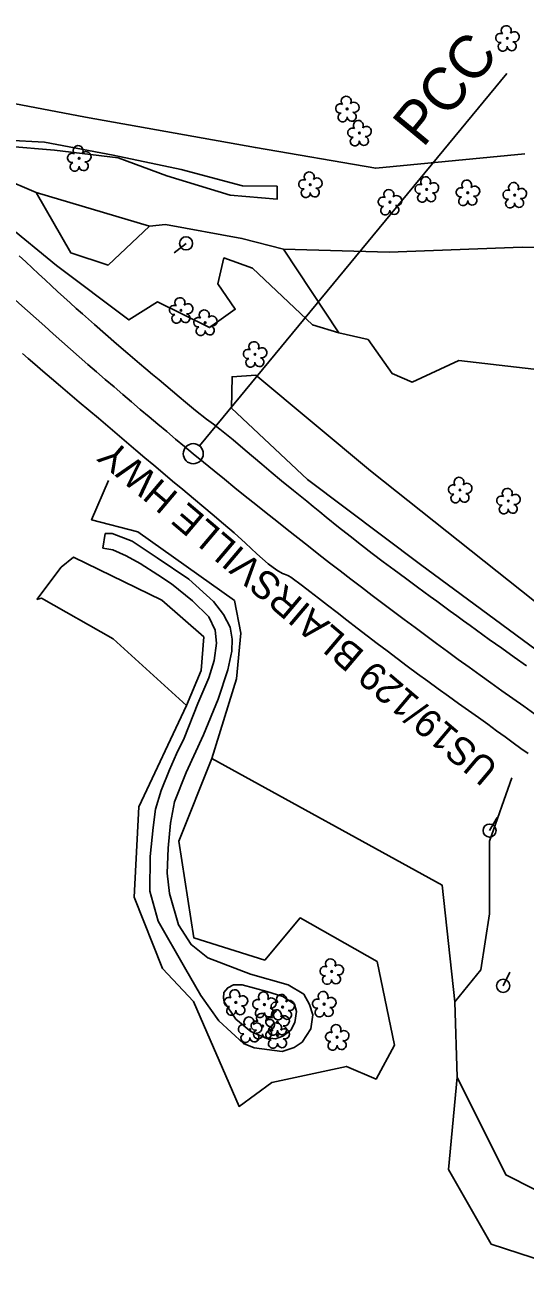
# Model space of a CAD drawing. Extents: x 477009 to 479892, y 492858 to 496862.
# Drawn here: x 479085.5 to 479272.5, y 493587.2 to 494052.3 of the extents above; entities that cross this region are included whole.
import ezdxf

# ---------------------------------------------------------------- set-up
doc = ezdxf.new("R2010")
doc.units = 0
for name, color, linetype in [('Exist Horizontal Alignment', 7, 'Continuous'), ('Exist Other Culture Fence Line', 7, 'Continuous'), ('Exist Roads EOP', 7, 'Continuous'), ('Exist Roads EOP Text', 7, 'Continuous'), ('Exist Roads Soil', 7, 'Continuous'), ('Exist Utilities Power Pole CELL', 7, 'Continuous'), ('Exist Vegetation Hedge Row', 7, 'Continuous'), ('Exist Vegetation Tree CELL', 7, 'Continuous'), ('Exist Vegetation Woods Line', 7, 'Continuous')]:
    doc.layers.add(name, color=color, linetype=linetype)

msp = doc.modelspace()

# ---------------------------------------------------------------- linework, layer by layer
at = {"layer": 'Exist Horizontal Alignment'}
msp.add_line((479150.84, 493895.18), (479265.62, 494034.24), dxfattribs=at)
msp.add_circle((479148.46, 493892.29), 3.75, dxfattribs=at)
for centre, radius, start, end in [((480415.92, 495427.95), 1991.17, 222.54643, 230.46528), ((480448.9, 495467.9), 2042.96, 230.46528, 239.46392)]:
    msp.add_arc(centre, radius, start, end, dxfattribs=at)
at = {"layer": 'Exist Other Culture Fence Line'}
for points in [[(479108.16, 494017.94), (479070.79, 494024.96), (479052.06, 494028.2), (479035.55, 494044.67), (479005.51, 494074.07), (478956.05, 494123.48), (478945.66, 494161.44), (478974.21, 494187.61), (479002.57, 494213.48)], [(479108.16, 494017.94), (479171.66, 494006.53), (479216.64, 493998.87), (479272.39, 494004.19)]]:
    msp.add_lwpolyline(points, dxfattribs=at)
at = {"layer": 'Exist Roads EOP'}
for points in [[(479273.02, 493813.09), (479268.38, 493816.36), (479263.76, 493819.66), (479259.12, 493822.99), (479254.37, 493826.41), (479251.95, 493828.15), (479249.5, 493829.92), (479247.02, 493831.72), (479244.52, 493833.54), (479241.99, 493835.38), (479239.47, 493837.22), (479237.01, 493839.02), (479232.25, 493842.48), (479227.75, 493845.78), (479223.52, 493848.92), (479219.45, 493851.98), (479215.38, 493855.06), (479211.29, 493858.21), (479207.12, 493861.47), (479202.78, 493864.92), (479198.14, 493868.65), (479195.74, 493870.59), (479193.31, 493872.56), (479190.85, 493874.56), (479188.36, 493876.59), (479185.92, 493878.57), (479181.49, 493882.21), (479177.6, 493885.42), (479174.1, 493888.33), (479170.92, 493891), (479167.8, 493893.65), (479163.35, 493897.42), (479160.82, 493899.5), (479158.43, 493901.39), (479155.97, 493903.29), (479153.43, 493905.23), (479149.31, 493908.45), (479145.5, 493911.58), (479143.16, 493913.54), (479140.68, 493915.63), (479138.2, 493917.72), (479135.7, 493919.82), (479133.2, 493921.91), (479130.74, 493923.98), (479128.38, 493925.97), (479123.95, 493929.75), (479119.77, 493933.35), (479115.68, 493936.87), (479111.5, 493940.51), (479107.04, 493944.46), (479104.73, 493946.52), (479102.41, 493948.61), (479100.09, 493950.72), (479097.76, 493952.85), (479095.41, 493955), (479093.04, 493957.18), (479090.65, 493959.39), (479088.24, 493961.63), (479085.82, 493963.88), (479083.41, 493966.11)], [(479273.65, 493780.38), (479270.93, 493782.31), (479268.06, 493784.37), (479265.03, 493786.58), (479261.85, 493788.9), (479258.52, 493791.31), (479255.03, 493793.8), (479251.39, 493796.39), (479247.65, 493799.04), (479243.86, 493801.75), (479240.02, 493804.52), (479236.13, 493807.33), (479232.24, 493810.17), (479228.41, 493813.01), (479224.62, 493815.83), (479220.89, 493818.65), (479217.17, 493821.47), (479213.43, 493824.34), (479209.68, 493827.23), (479205.91, 493830.16), (479202.2, 493833.04), (479198.66, 493835.79), (479195.27, 493838.4), (479192.04, 493840.88), (479189.23, 493843.03), (479184.87, 493846.25), (479184.09, 493846.7), (479183.76, 493846.85), (479182.54, 493847.27), (479181.78, 493847.62), (479179.67, 493848.88), (479176.5, 493851.2), (479172.16, 493854.92), (479167.96, 493858.86), (479163.74, 493862.76), (479159.8, 493866.17), (479155.52, 493869.74), (479152.38, 493872.36), (479148.56, 493875.53), (479144.51, 493878.89), (479140.68, 493882.08), (479137.07, 493885.12), (479133.66, 493887.98), (479130.34, 493890.79), (479126.97, 493893.65), (479123.54, 493896.57), (479120.05, 493899.53), (479116.53, 493902.53), (479112.99, 493905.53), (479109.44, 493908.54), (479105.86, 493911.56), (479102.32, 493914.54), (479098.87, 493917.46), (479095.52, 493920.32), (479092.25, 493923.1), (479089.26, 493925.68), (479086.73, 493927.88), (479084.65, 493929.72)]]:
    msp.add_lwpolyline(points, dxfattribs=at)
at = {"layer": 'Exist Roads Soil'}
for points in [[(479115.47, 493862.54), (479118.17, 493862.52), (479125.58, 493859.66), (479135.01, 493853.38), (479146.79, 493845.44), (479156.04, 493837.13), (479159.74, 493832.23), (479162.21, 493827.49), (479163.04, 493823.1), (479162.93, 493818.6), (479161.34, 493811.63), (479157.76, 493800.7), (479152.24, 493787.36), (479145.79, 493773.32), (479141.47, 493762.36), (479139.91, 493754.41), (479139.03, 493745.1), (479138.68, 493735.69), (479139.53, 493728.14), (479142.95, 493716.46), (479147.68, 493709.09), (479153.89, 493704.09), (479169.8, 493698.05), (479183.93, 493694.02), (479189.75, 493690.55), (479191.96, 493686.74), (479193.12, 493682.84), (479192.44, 493677.59), (479189.13, 493672.66), (479186.17, 493670.59), (479181.75, 493669.19), (479171.25, 493670.54), (479167.28, 493672.1), (479158, 493680.62), (479151.25, 493690.09), (479145.24, 493700.61), (479135.39, 493717.85), (479132.28, 493729.06), (479132.29, 493741.91), (479133.52, 493752.81), (479134.29, 493759.61), (479136.4, 493766.63), (479139.63, 493774.27), (479142.25, 493780.22), (479145, 493786.14), (479150.14, 493799.06), (479154.26, 493808.63), (479156.32, 493815.04), (479157.12, 493821.63), (479156.69, 493826.48), (479154.24, 493831.35), (479148.16, 493837.35), (479140.35, 493843.73), (479135.27, 493847.12), (479128.62, 493851.25), (479123.39, 493854.2), (479118.35, 493856.45), (479114.67, 493857.07), (479115.47, 493862.54)], [(479159.98, 493687.75), (479164.43, 493681.27), (479169.94, 493676.57), (479175.04, 493674.43), (479179.18, 493673.84), (479181.96, 493674.9), (479184.92, 493677.07), (479186.43, 493680), (479187.08, 493684.1), (479186.29, 493686.82), (479181.92, 493689.67), (479175.94, 493691.53), (479166.8, 493694.01), (479163.54, 493694), (479161.32, 493692.97), (479159.94, 493691.13), (479159.76, 493689.09), (479159.98, 493687.75)]]:
    msp.add_lwpolyline(points, dxfattribs=at)
at = {"layer": 'Exist Utilities Power Pole CELL'}
for p, q in [((479145.76, 493970.8), (479141.37, 493967.28)), ((479145.76, 493970.8), (479145.76, 493970.8)), ((479259.22, 493751.62), (479262.06, 493756.47)), ((479259.22, 493751.62), (479259.22, 493751.62)), ((479264.31, 493693.67), (479266.8, 493698.71)), ((479264.31, 493693.67), (479264.31, 493693.67))]:
    msp.add_line(p, q, dxfattribs=at)
for centre in [(479145.76, 493970.8), (479259.22, 493751.62), (479264.31, 493693.67)]:
    msp.add_circle(centre, 2.45, dxfattribs=at)
at = {"layer": 'Exist Vegetation Hedge Row'}
for points in [[(479096.63, 494005.63), (479078.72, 494007.07), (479064.9, 494009.62), (479055.61, 494011.94), (479052.88, 494010.84), (479049.89, 494007.25), (479044.21, 494012.52), (479046.53, 494016.23), (479052.16, 494014.3), (479055.59, 494012.7), (479063, 494013.98), (479078.8, 494009.34), (479092.9, 494008.55)], [(479092.9, 494008.55), (479118.49, 494003.72), (479143.95, 493998.32), (479166.91, 493992.28), (479179.82, 493992.14), (479179.88, 493987.32), (479162.28, 493988.83), (479138.64, 493995.99), (479120.41, 494002.76), (479096.63, 494005.63)], [(479078.52, 493977.98), (479068.39, 493987.61), (479068.42, 493990.58), (479067.35, 493992.62), (479076.93, 493995.26), (479089.7, 493989.76)], [(479202.84, 493937.4), (479192.99, 493940.45), (479170.55, 493961.53), (479159.94, 493965.4), (479157.61, 493955.73), (479164.16, 493946.19), (479154.57, 493939.38), (479135.06, 493949.04), (479124.4, 493942.25), (479097.29, 493962.49), (479078.52, 493977.98)], [(479132.06, 493977.26), (479138.05, 493977.9), (479166.63, 493972.65), (479182.16, 493968.66)], [(479171.8, 493921.62), (479214.74, 493885.94), (479276, 493837.28), (479371.67, 493764.52), (479365.39, 493760.73), (479353.23, 493765.86), (479299.39, 493802.32), (479233.34, 493850.88), (479191.14, 493882.61), (479162.76, 493909.29), (479162.97, 493921.03), (479171.8, 493921.62)], [(479155.42, 493778.48), (479164.56, 493808.22), (479166.22, 493825.31), (479163.89, 493837.46), (479127.8, 493863.11), (479110.48, 493867.61), (479116.76, 493882.24)], [(479089.96, 493837.85), (479099.11, 493849.98), (479103.69, 493853.62), (479136.77, 493837.68), (479152.39, 493823.9), (479151.44, 493811.41), (479145.89, 493798.32)], [(479267.52, 493771.33), (479259.14, 493747.61), (479259.22, 493720.49), (479255.94, 493699.61), (479246.2, 493687.72)], [(479247.14, 493659.54), (479265.35, 493623.09), (479308.43, 493601.29)]]:
    msp.add_lwpolyline(points, dxfattribs=at)
at = {"layer": 'Exist Vegetation Tree CELL'}
for p, q in [((479265.84, 494047.32), (479265.84, 494047.32)), ((479206, 494021), (479206, 494021)), ((479210.56, 494011.99), (479210.56, 494011.99)), ((479105.8, 494002.55), (479105.8, 494002.55)), ((479192.19, 493992.72), (479192.19, 493992.72)), ((479235.71, 493990.95), (479235.71, 493990.95)), ((479221.95, 493986.18), (479221.95, 493986.18)), ((479251.07, 493989.69), (479251.07, 493989.69)), ((479268.59, 493988.81), (479268.59, 493988.81)), ((479143.86, 493945.81), (479143.86, 493945.81)), ((479152.92, 493941.21), (479152.92, 493941.21)), ((479171.52, 493929.38), (479171.52, 493929.38)), ((479248.17, 493878.76), (479248.17, 493878.76)), ((479266.21, 493874.63), (479266.21, 493874.63)), ((479200.18, 493699.01), (479200.18, 493699.01)), ((479164.37, 493687.46), (479164.37, 493687.46)), ((479175.06, 493686.66), (479175.06, 493686.66)), ((479181.85, 493685.73), (479181.85, 493685.73)), ((479197.38, 493686.83), (479197.38, 493686.83)), ((479174.38, 493678.64), (479174.38, 493678.64)), ((479179.93, 493680.01), (479179.93, 493680.01)), ((479169.66, 493677.32), (479169.66, 493677.32)), ((479179.96, 493675.17), (479179.96, 493675.17)), ((479202.22, 493674.48), (479202.22, 493674.48))]:
    msp.add_line(p, q, dxfattribs=at)
for centre in [(479265.84, 494047.32), (479206, 494021), (479210.56, 494011.99), (479105.8, 494002.55), (479192.19, 493992.72), (479235.71, 493990.95), (479251.07, 493989.69), (479221.95, 493986.18), (479268.59, 493988.81), (479143.86, 493945.81), (479152.92, 493941.21), (479171.52, 493929.38), (479248.17, 493878.76), (479266.21, 493874.63), (479200.18, 493699.01), (479164.37, 493687.46), (479175.06, 493686.66), (479181.85, 493685.73), (479197.38, 493686.83), (479174.38, 493678.64), (479179.93, 493680.01), (479169.66, 493677.32), (479179.96, 493675.17), (479202.22, 493674.48)]:
    msp.add_circle(centre, 0.326, dxfattribs=at)
for centre, radius, start, end in [((479265.45, 494050.2), 1.86, 330.1651, 219.7134), ((479263.23, 494047.48), 1.73, 62.6636, 279.3457), ((479264.13, 494044.2), 1.69, 111.5671, 6.231), ((479267.51, 494044.42), 1.7, 181.2822, 74.56), ((479268.39, 494047.91), 1.9, 257.1011, 134.1999), ((479203.4, 494021.15), 1.73, 62.6636, 279.3457), ((479205.62, 494023.87), 1.86, 330.1651, 219.7134), ((479208.55, 494021.59), 1.9, 257.1011, 134.1999), ((479204.3, 494017.88), 1.69, 111.5671, 6.231), ((479207.67, 494018.1), 1.7, 181.2822, 74.56), ((479207.95, 494012.14), 1.73, 62.6636, 279.3457), ((479210.17, 494014.86), 1.86, 330.1651, 219.7134), ((479213.11, 494012.58), 1.9, 257.1011, 134.1999), ((479208.85, 494008.87), 1.69, 111.5671, 6.231), ((479212.23, 494009.09), 1.7, 181.2822, 74.56), ((479103.2, 494002.7), 1.73, 62.6636, 279.3457), ((479105.42, 494005.42), 1.86, 330.1651, 219.7134), ((479108.35, 494003.14), 1.9, 257.1011, 134.1999), ((479104.1, 493999.43), 1.69, 111.5671, 6.231), ((479107.47, 493999.65), 1.7, 181.2822, 74.56), ((479189.59, 493992.87), 1.73, 62.6636, 279.3457), ((479191.81, 493995.59), 1.86, 330.1651, 219.7134), ((479194.74, 493993.31), 1.9, 257.1011, 134.1999), ((479235.33, 493993.83), 1.86, 330.1651, 219.7134), ((479190.49, 493989.6), 1.69, 111.5671, 6.231), ((479193.86, 493989.82), 1.7, 181.2822, 74.56), ((479221.56, 493989.05), 1.86, 330.1651, 219.7134), ((479233.11, 493991.11), 1.73, 62.6636, 279.3457), ((479238.26, 493991.54), 1.9, 257.1011, 134.1999), ((479248.46, 493989.85), 1.73, 62.6636, 279.3457), ((479250.68, 493992.57), 1.86, 330.1651, 219.7134), ((479253.62, 493990.28), 1.9, 257.1011, 134.1999), ((479265.99, 493988.96), 1.73, 62.6636, 279.3457), ((479268.21, 493991.68), 1.86, 330.1651, 219.7134), ((479271.14, 493989.39), 1.9, 257.1011, 134.1999), ((479219.34, 493986.33), 1.73, 62.6636, 279.3457), ((479224.5, 493986.77), 1.9, 257.1011, 134.1999), ((479234.01, 493987.83), 1.69, 111.5671, 6.231), ((479237.38, 493988.05), 1.7, 181.2822, 74.56), ((479249.36, 493986.57), 1.69, 111.5671, 6.231), ((479252.74, 493986.79), 1.7, 181.2822, 74.56), ((479266.89, 493985.68), 1.69, 111.5671, 6.231), ((479270.26, 493985.91), 1.7, 181.2822, 74.56), ((479220.24, 493983.06), 1.69, 111.5671, 6.231), ((479223.62, 493983.28), 1.7, 181.2822, 74.56), ((479143.47, 493948.68), 1.86, 330.1651, 219.7134), ((479146.41, 493946.4), 1.9, 257.1011, 134.1999), ((479141.25, 493945.96), 1.73, 62.6636, 279.3457), ((479142.15, 493942.69), 1.69, 111.5671, 6.231), ((479145.53, 493942.91), 1.7, 181.2822, 74.56), ((479152.54, 493944.09), 1.86, 330.1651, 219.7134), ((479155.47, 493941.8), 1.9, 257.1011, 134.1999), ((479150.32, 493941.37), 1.73, 62.6636, 279.3457), ((479151.22, 493938.09), 1.69, 111.5671, 6.231), ((479154.6, 493938.31), 1.7, 181.2822, 74.56), ((479171.13, 493932.25), 1.86, 330.1651, 219.7134), ((479168.91, 493929.53), 1.73, 62.6636, 279.3457), ((479174.07, 493929.97), 1.9, 257.1011, 134.1999), ((479169.81, 493926.26), 1.69, 111.5671, 6.231), ((479173.19, 493926.48), 1.7, 181.2822, 74.56), ((479247.78, 493881.63), 1.86, 330.1651, 219.7134), ((479245.56, 493878.91), 1.73, 62.6636, 279.3457), ((479250.72, 493879.35), 1.9, 257.1011, 134.1999), ((479265.83, 493877.51), 1.86, 330.1651, 219.7134), ((479246.46, 493875.64), 1.69, 111.5671, 6.231), ((479249.84, 493875.86), 1.7, 181.2822, 74.56), ((479263.61, 493874.79), 1.73, 62.6636, 279.3457), ((479268.76, 493875.22), 1.9, 257.1011, 134.1999), ((479264.51, 493871.51), 1.69, 111.5671, 6.231), ((479267.88, 493871.73), 1.7, 181.2822, 74.56), ((479199.79, 493701.88), 1.86, 330.1651, 219.7134), ((479197.57, 493699.16), 1.73, 62.6636, 279.3457), ((479198.47, 493695.89), 1.69, 111.5671, 6.231), ((479201.85, 493696.11), 1.7, 181.2822, 74.56), ((479202.73, 493699.6), 1.9, 257.1011, 134.1999), ((479161.76, 493687.62), 1.73, 62.6636, 279.3457), ((479163.98, 493690.34), 1.86, 330.1651, 219.7134), ((479166.92, 493688.05), 1.9, 257.1011, 134.1999), ((479172.45, 493686.81), 1.73, 62.6636, 279.3457), ((479174.67, 493689.53), 1.86, 330.1651, 219.7134), ((479177.61, 493687.24), 1.9, 257.1011, 134.1999), ((479179.24, 493685.88), 1.73, 62.6636, 279.3457), ((479181.46, 493688.6), 1.86, 330.1651, 219.7134), ((479184.4, 493686.32), 1.9, 257.1011, 134.1999), ((479194.77, 493686.99), 1.73, 62.6636, 279.3457), ((479196.99, 493689.71), 1.86, 330.1651, 219.7134), ((479199.93, 493687.42), 1.9, 257.1011, 134.1999), ((479162.66, 493684.34), 1.69, 111.5671, 6.231), ((479166.04, 493684.56), 1.7, 181.2822, 74.56), ((479173.36, 493683.53), 1.69, 111.5671, 6.231), ((479174, 493681.51), 1.86, 330.1651, 219.7134), ((479176.73, 493683.76), 1.7, 181.2822, 74.56), ((479179.55, 493682.88), 1.86, 330.1651, 219.7134), ((479180.14, 493682.61), 1.69, 111.5671, 6.231), ((479183.52, 493682.83), 1.7, 181.2822, 74.56), ((479195.68, 493683.71), 1.69, 111.5671, 6.231), ((479199.05, 493683.93), 1.7, 181.2822, 74.56), ((479167.05, 493677.47), 1.73, 62.6636, 279.3457), ((479169.27, 493680.19), 1.86, 330.1651, 219.7134), ((479171.78, 493678.79), 1.73, 62.6636, 279.3457), ((479172.21, 493677.91), 1.9, 257.1011, 134.1999), ((479177.32, 493680.16), 1.73, 62.6636, 279.3457), ((479176.93, 493679.23), 1.9, 257.1011, 134.1999), ((479178.23, 493676.88), 1.69, 111.5671, 6.231), ((479179.57, 493678.04), 1.86, 330.1651, 219.7134), ((479181.6, 493677.11), 1.7, 181.2822, 74.56), ((479182.48, 493680.59), 1.9, 257.1011, 134.1999), ((479201.84, 493677.35), 1.86, 330.1651, 219.7134), ((479167.96, 493674.2), 1.69, 111.5671, 6.231), ((479171.33, 493674.42), 1.7, 181.2822, 74.56), ((479172.68, 493675.52), 1.69, 111.5671, 6.231), ((479176.06, 493675.74), 1.7, 181.2822, 74.56), ((479177.35, 493675.32), 1.73, 62.6636, 279.3457), ((479178.26, 493672.05), 1.69, 111.5671, 6.231), ((479181.63, 493672.27), 1.7, 181.2822, 74.56), ((479182.51, 493675.76), 1.9, 257.1011, 134.1999), ((479199.62, 493674.63), 1.73, 62.6636, 279.3457), ((479204.77, 493675.07), 1.9, 257.1011, 134.1999), ((479200.52, 493671.36), 1.69, 111.5671, 6.231), ((479203.9, 493671.58), 1.7, 181.2822, 74.56)]:
    msp.add_arc(centre, radius, start, end, dxfattribs=at)
at = {"layer": 'Exist Vegetation Woods Line'}
for points in [[(479132.06, 493977.26), (479116.61, 493962.67), (479102.74, 493967.23), (479089.7, 493989.76)], [(479089.7, 493989.76), (479132.06, 493977.26)], [(479182.16, 493968.66), (479221.74, 493967.55), (479271.37, 493969.44), (479303.26, 493968.48), (479365.35, 493947.92)], [(479346.74, 493911.74), (479294.06, 493921.78), (479247.71, 493927.02), (479230.29, 493918.95), (479222.8, 493922.23), (479213.79, 493934.9), (479202.84, 493937.4), (479182.16, 493968.66)], [(479089.96, 493837.85), (479091.67, 493838.31), (479118.55, 493823.13), (479145.89, 493798.32)], [(479145.89, 493798.32), (479128.12, 493760.46), (479126.39, 493726.78), (479137, 493700.11), (479148.49, 493687.85), (479165.58, 493648.63), (479177.85, 493657.58), (479205.71, 493663.61), (479216.8, 493658.89), (479223.74, 493671.48), (479217.14, 493702.7), (479188.4, 493719.02), (479175.2, 493703.29), (479148.61, 493711.6), (479143.08, 493747.7), (479155.42, 493778.48)], [(479155.42, 493778.48), (479241.47, 493731.28), (479246.2, 493687.72), (479247.14, 493659.54), (479243.81, 493625.08), (479259.84, 493597.24), (479290.89, 493587.19)]]:
    msp.add_lwpolyline(points, dxfattribs=at)

# ---------------------------------------------------------------- texts
at = {"layer": 'Exist Horizontal Alignment'}
msp.add_text('PCC', height=16, rotation=50.4653, dxfattribs=at).set_placement((479234.27, 494006.17))
at = {"layer": 'Exist Roads EOP Text'}
msp.add_text('US19/129 BLAIRSVILLE HWY', height=10.4, rotation=139.7167, dxfattribs=at).set_placement((479263.1, 493775.65))

doc.saveas('drawing.dxf')
